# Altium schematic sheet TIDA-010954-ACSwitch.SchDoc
size 431 x 279 mm; Date: Not shown in title block; ApprovedBy: Not shown in title block; CheckedBy: Not shown in title block; Author: Not shown in title block; CompanyName: Not shown in title block; Engineer: Not shown in title block; Organization: Not shown in title block; Address1: Not shown in title block; Address2: Not shown in title block; Address3: Not shown in title block; Address4: Not shown in title block; DocumentNumber: 2; Revision: Use project parameter SCH_Rev; SheetNumber: 3; SheetTotal: 9; PageSetup: Record=PageOptions¦CenterHorizontal=True¦CenterVertical=True¦PrintScale=1.00¦XCorrection=1.00¦YCorrection=1.00¦PrintKind=0¦BorderSize=5000000¦LeftOffset=0¦BottomOffset=0¦Orientation=2¦PaperLength=1000¦PaperWidth=1000¦Scale=100¦PaperSource=15¦PrintQuality=600¦MediaType=1¦DitherType=10¦PaperKind=Letter¦PrintScaleMode=1
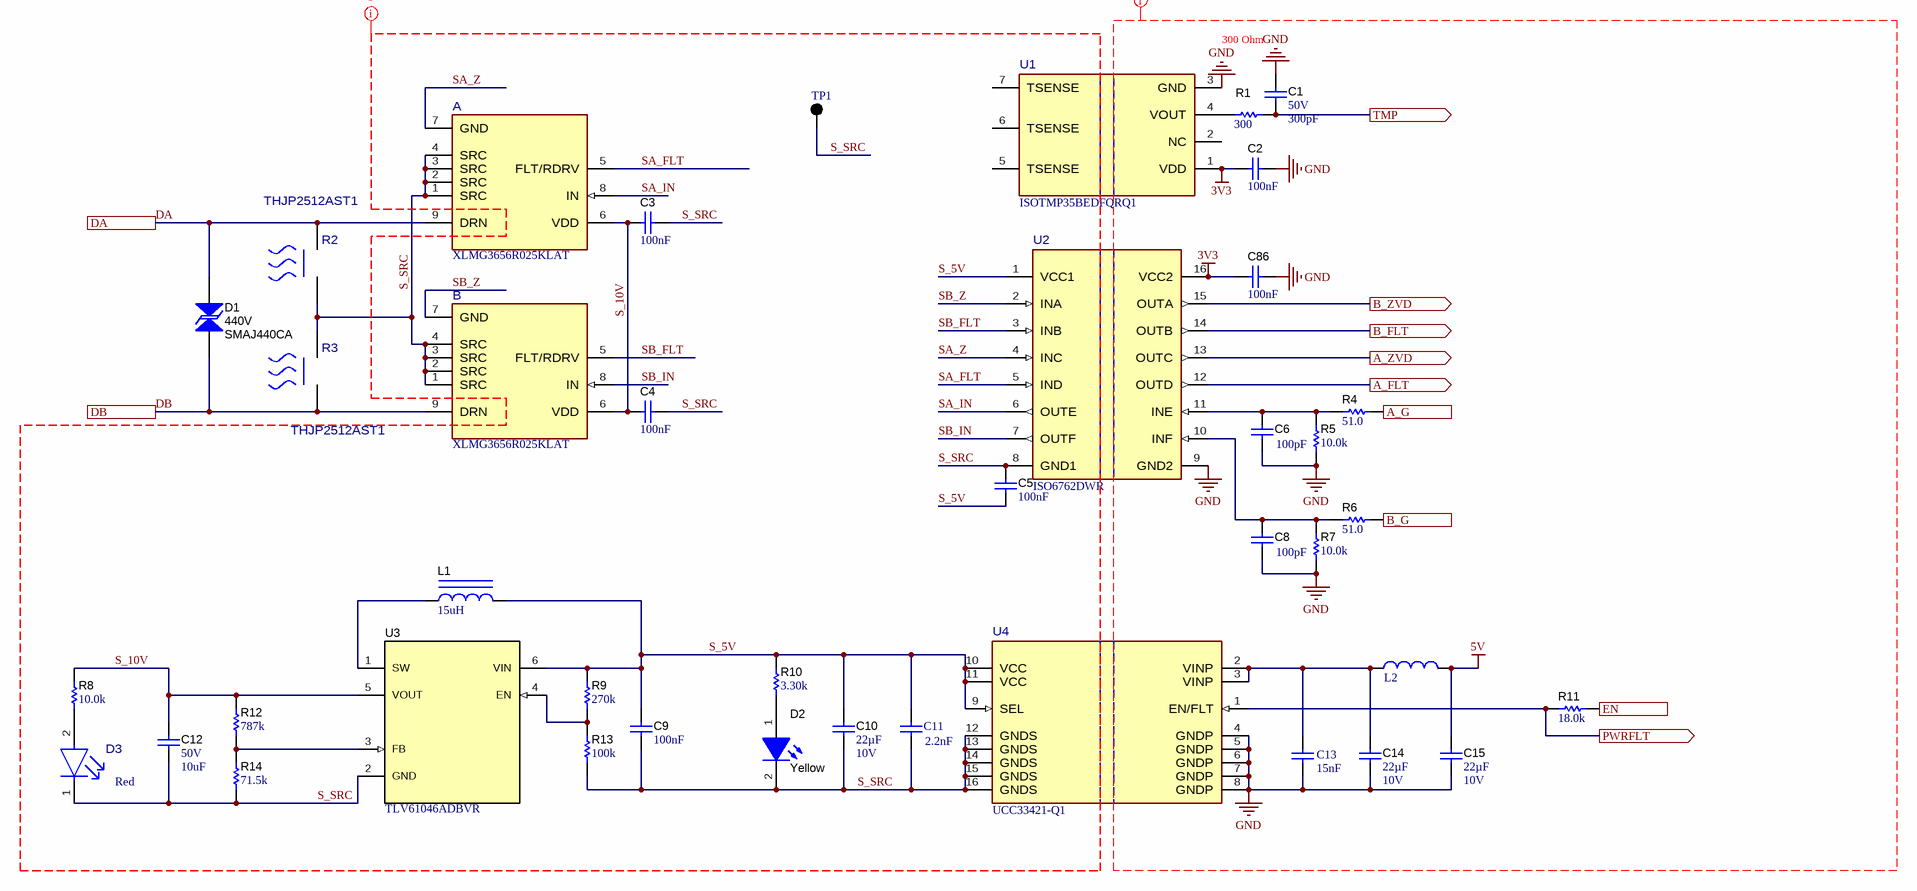
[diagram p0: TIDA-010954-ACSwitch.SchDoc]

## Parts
A  XLMG3656R025KLAT  [KLA0009A-MFG]
B  XLMG3656R025KLAT  [KLA0009A-MFG]
C1  VDC_V: 50V  ValueDisplayed: 300pF  [0603]  (hidden comment: GRM1885C1H301JA01D)
C2  Cap_F: 100nF  [0603]  (hidden comment: CGA3E2X7R1E104K080AA)
C3  Cap_F: 100nF  [0603]  (hidden comment: CGA3E2X7R1E104K080AA)
C4  Cap_F: 100nF  [0603]  (hidden comment: CGA3E2X7R1E104K080AA)
C5  Cap_F: 100nF  [0603]  (hidden comment: CGA3E2X7R1E104K080AA)
C6  ValueDisplayed: 100pF  [0603]  (hidden comment: GRM1885C1H101JA01D)
C8  ValueDisplayed: 100pF  [0603]  (hidden comment: GRM1885C1H101JA01D)
C9  Cap_F: 100nF  [0603]  (hidden comment: CGA3E2X7R1E104K080AA)
C10  Cap_F: 22µF  VDC_V: 10V  [0805_HV]  (hidden comment: GRM21BZ71A226ME15L)
C11  Cap_F: 2.2nF  [WCAP-CSGP_0402_L1W0.5H0.5]  (hidden comment: 885012205063)
C12  VDC_V: 50V  ValueDisplayed: 10uF  [1206_180]  (hidden comment: GRT31CR61H106KE01L)
C13  Cap_F: 15nF  [WCAP-CSGP_0402_L1W0.5H0.5]  (hidden comment: 885012205051)
C14  Cap_F: 22µF  VDC_V: 10V  [0805_HV]  (hidden comment: GRM21BZ71A226ME15L)
C15  Cap_F: 22µF  VDC_V: 10V  [0805_HV]  (hidden comment: GRM21BZ71A226ME15L)
C86  Cap_F: 100nF  [0603]  (hidden comment: CGA3E2X7R1E104K080AA)
D1  SMAJ440CA  value 440V  [SMA_Bi]
D2  value Yellow  [APT1608_Yellow]  (hidden comment: APT1608SYCK)
D3  Color: Red  [FP-APG1608SURKC_T_0603-MFG]  (hidden comment: APG1608SURKC/T)
L1  ValueDisplayed: 15uH  [SDR0302]  (hidden comment: SDR0302-150ML)
L2  74479763222  [WE-PMI_0603_L1.6W0.8H0.8]  (value not drawn)
R1  ValueDisplayed: 300  [0603]  (hidden comment: RC0603FR-07300RL)
R2  THJP2512AST1  [FP-THJP2512AST1_2512-MFG]
R3  THJP2512AST1  [FP-THJP2512AST1_2512-MFG]
R4  ValueDisplayed: 51.0  [0603]  (hidden comment: RC0603FR-0751RL)
R5  ValueDisplayed: 10.0k  [0603]  (hidden comment: RC0603FR-0710KL)
R6  ValueDisplayed: 51.0  [0603]  (hidden comment: RC0603FR-0751RL)
R7  ValueDisplayed: 10.0k  [0603]  (hidden comment: RC0603FR-0710KL)
R8  ValueDisplayed: 10.0k  [0603]  (hidden comment: RC0603FR-0710KL)
R9  ValueDisplayed: 270k  [0603]  (hidden comment: RC0603FR-07270KL)
R10  ValueDisplayed: 3.30k  [0603]  (hidden comment: RC0603FR-073K3L)
R11  ValueDisplayed: 18.0k  [0603]  (hidden comment: RC0603FR-0718KL)
R12  ValueDisplayed: 787k  [0603]  (hidden comment: RC0603FR-07787KL)
R13  ValueDisplayed: 100k  [0603]  (hidden comment: RC0603FR-07100KL)
R14  ValueDisplayed: 71.5k  [0603]  (hidden comment: RC0603FR-0771K5L)
TP1  5011  [Keystone5011]  (value not drawn)
U1  ISOTMP35BEDFQRQ1  [DFQ0007A-MFG]
U2  ISO6762DWR  [DW0016A-MFG]
U3  TLV61046ADBVR  [DBV0006A_N]
U4  UCC33421-Q1  [DWX0016A-MFG]

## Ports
A_FLT (out), A_G (in), A_ZVD (out), B_FLT (out), B_G (in), B_ZVD (out), DA, DB, EN (in), PWRFLT (out), TMP (out)

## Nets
3V3: C2.1 C86.1 U1.1(VDD) U2.16(VCC2)
5V: C15.1 L2.2
GND: C1.2 C2.2 C6.2 C8.2 C13.1 C14.2 C15.2 C86.2 R5.1 R7.1 U1.3(GND) U2.9(GND2) U4.4(GNDP) U4.5(GNDP) U4.6(GNDP) U4.7(GNDP) U4.8(GNDP)
A_FLT: U2.12(OUTD) ; port A_FLT
A_G: R4.2 ; port A_G
A_ZVD: U2.13(OUTC) ; port A_ZVD
B_FLT: U2.14(OUTB) ; port B_FLT
B_G: R6.2 ; port B_G
B_ZVD: U2.15(OUTA) ; port B_ZVD
DA: A.9(DRN) D1.2 R2.2 ; port DA
DB: B.9(DRN) D1.1 R3.1 ; port DB
EN: R11.2 ; port EN
PWRFLT: R11.1 U4.1(EN/FLT) ; port PWRFLT
S_5V: C5.1 C9.2 C10.1 C11.2 L1.2 R9.2 R10.2 U2.1(VCC1) U3.6(VIN) U4.9(SEL) U4.10(VCC) U4.11(VCC)
S_10V: A.6(VDD) B.6(VDD) C3.1 C4.1 C12.1 R8.2 R12.2 U3.5(VOUT)
S_SRC: A.1(SRC) A.2(SRC) A.3(SRC) A.4(SRC) B.1(SRC) B.2(SRC) B.3(SRC) B.4(SRC) C3.2 C4.2 C5.2 C9.1 C10.2 C11.1 C12.2 D2.2(K) D3.1(CATHODE) R2.1 R3.2 R13.1 R14.1 TP1.1 U2.8(GND1) U3.2(GND) U4.12(GNDS) U4.13(GNDS) U4.14(GNDS) U4.15(GNDS) U4.16(GNDS)
SA_FLT: A.5(FLT/RDRV) U2.5(IND)
SA_IN: A.8(IN) U2.6(OUTE)
SA_Z: A.7(GND) U2.4(INC)
SB_FLT: B.5(FLT/RDRV) U2.3(INB)
SB_IN: B.8(IN) U2.7(OUTF)
SB_Z: B.7(GND) U2.2(INA)
TMP: C1.1 R1.2 ; port TMP
NetC6_1: C6.1 R4.1 R5.2 U2.11(INE)
NetC8_1: C8.1 R6.1 R7.2 U2.10(INF)
NetC13_2: C13.2 C14.1 L2.1 U4.2(VINP) U4.3(VINP)
NetD2_1: D2.1(A) R10.1
NetD3_2: D3.2(ANODE) R8.1
NetL1_1: L1.1 U3.1(SW)
NetR1_1: R1.1 U1.4(VOUT)
NetR9_1: R9.1 R13.2 U3.4(EN)
NetR12_1: R12.1 R14.2 U3.3(FB)

Not connected (* = marked no-connect by the designer): U1 2(NC) 5(TSENSE) 6(TSENSE) 7(TSENSE)

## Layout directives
net class SW_SRC: DA, DB, S_5V, S_10V, S_SRC, SA_FLT, SA_IN, SA_Z, SB_FLT, SB_IN, SB_Z
net class LV: 3V3, 5V, GND

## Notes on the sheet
- 300 Ohm

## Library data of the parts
A B = CMP-0120607-2: Manufacturer: Texas Instruments; Part Number: LMG365x; SizeZ_mm: 2.35mm; AEC Qualified: No; Standoff Height: 0.1mm; AEC Category: Q200; CompType: IC
C1 = CMP-0007206-4: CAP, CERM, 300 pF, 50 V, +/- 5%, C0G/NP0, 0603; Manufacturer: MuRata; TaMin_C: -55°C; Polarized: N; SizeAreaWB_mm2: 4.68; Value1: Unknown; U/M: EA; Value: 300pF; TaMax_C: 125°C; SizeZ_mm: 1; SizeX_mm: 1.6; SizeY_mm: 0.8; SizeArea_mm2: 1.28; AEC Category: Q200
C2-C5 C9 C86 = CMP-0007077-5: CAP, CERM, 0.1 uF, 25 V, +/- 10%, X7R, AEC-Q200 Grade 1, 0603; Manufacturer: TDK; TaMin_C: -55°C; Polarized: N; SizeAreaWB_mm2: 4.68; Value1: Unknown; U/M: EA; Value: 0.1uF; TaMax_C: 125°C; SizeZ_mm: 1; SizeX_mm: 1.6; SizeY_mm: 0.8; Value2: 25V; SizeArea_mm2: 1.28; AEC Qualified: Y; AEC Category: Q200
C6 C8 = CMP-0007171-4: CAP, CERM, 100 pF, 50 V, +/- 5%, C0G/NP0, 0603; Manufacturer: MuRata; TaMin_C: -55°C; Polarized: N; SizeAreaWB_mm2: 4.68; Value1: Unknown; U/M: EA; Value: 100pF; TaMax_C: 125°C; SizeZ_mm: 1; SizeX_mm: 1.6; SizeY_mm: 0.8; Value2: 50V; SizeArea_mm2: 1.28; AEC Category: Q200
C10 C14 C15 = CMP-0008377-2: CAP, CERM, 22 uF, 10 V, +/- 20%, X7R, 0805; Manufacturer: MuRata; SizeY_mm: 1.25; Cap_Case: 0805; SizeArea_mm2: 2.5; AEC Qualified: N; AEC Category: Q200; ValueDisplayed: 22uF; TaMin_C: -55°C; SizeAreaWB_mm2: 6.75; Value1: Unknown; U/M: EA; Value: 22uF; TaMax_C: 125°C; SizeZ_mm: 1.45; SizeX_mm: 2
C11 = CMP-0119293-1: WCAP-CSGP Multilayer Ceramic Chip Capacitor, General Purpose, size 0402, X7R, 2.2nF, 50VDC; Manufacturer: Wurth Elektronik; Capacitance Tolerance: +/-10%; Case/Size Code: 0402; Dissipation Factor: 2.5%; Insulation Resistance: 10GOhm; Rated Voltage (DC): 50V; Technical Reference: X7R0402222K050DFCT10000
C12 = CMP-0009015-2: CAP, CERM, 10 uF, 50 V, +/- 10%, X5R, AEC-Q200 Grade 1, 1206; Manufacturer: MuRata; TaMin_C: -55°C; Polarized: N; SizeAreaWB_mm2: 10.92; Value1: Unknown; U/M: EA; Value: 10uF; TaMax_C: 85°C; SizeZ_mm: 1.8; SizeX_mm: 3.2; SizeY_mm: 1.6; Cap_Case: 1206; SizeArea_mm2: 5.12; AEC Qualified: Y; Cap_F: 10µF; AEC Grade: 1; AEC Category: Q200
C13 = CMP-0115362-1: WCAP-CSGP Multilayer Ceramic Chip Capacitor, General Purpose, size 0402, X7R, 15nF, 25VDC; Manufacturer: Wurth Elektronik; Capacitance Tolerance: +/-10%; Case/Size Code: 0402; Dissipation Factor: 3.5%; Insulation Resistance: 10GOhm; Rated Voltage (DC): 25V; Technical Reference: X7R0402153K025DFCT10000
D1 = CMP-0085046-1: Diode, TVS, Bi, 440 V, 713 Vc, 400 W, 0.6 A, SMA (non-polarized); Manufacturer: Littelfuse; Vbr_Max: 543V; Vbr_Min: 492V; Ppk: 400W; SizeY_mm: 2.575; Value1: 713V; SizeArea_mm2: 13.068125; SizeX_mm: 5.075; AEC Category: Q101; SizeAreaWB_mm2: 32.368125; SizeZ_mm: 2.65; RJA_CperW: 120; Ipp: 600mA; AEC Qualified: N
D2 = CMP-0002944-3: LED, Yellow, SMD; Manufacturer: Kingbright; Value2: 2.5V; Ir_A: 10µA; Tjmax_C: 85°C; Value1: W; Io_A: 20mA; Vr_V: 5V; Angle: 120
D3 = CMP-0091305-2: Red 630nm LED Indication - Discrete 2V 0603 (1608 Metric); Manufacturer: Kingbright; AEC Qualified: No; Import Ts: 1521847491; Forward Current: 20mA; Vr_V: 5V; Ciiva Ids: 1546259; Luminous Intensity: 110mcd; Power_TotalModule: 75mW; Tjmax_C: 115°C; Led Orientation: Top View; SizeZ_mm: 0.28mm; LambdaP: 645nm; Angle: 120°
L1 = CMP-0057419-2: Inductor, Drum Core, Ferrite, 15 uH, 0.65 A, 0.4 ohm, SMD; Manufacturer: Bourns; Isat: 0.86A @ 10% inductance drop; Irms: 0.65A @ 40C rise; Green_Lifecycle: Active; SizeAreaWB_mm2: 15.2; DCR_ohm: 4d; Green_REACh: Passed; Value1: 0.4 ohm; Value: 15uH; Imax_A: 6.5dA; SizeZ_mm: 2.5; SizeX_mm: 3; SizeY_mm: 2.8; Value2: 0.65A; SizeArea_mm2: 8.4; Ind_H: 15µH; AEC Category: Q200
L2 = CMP-0100992-1: WE-PMI SMT Power Multilayer Inductor, size 0603, 2.2uH, 0.8A, 375mOhm; Manufacturer: Wurth Elektronik; Case/Size Code: 0603; Inductance Tolerance: 20%; Q Factor: 15; Saturation Current: 0.28A; Self Resonant Frequency: 80MHz; Type: Low RDC
R1 = CMP-0023013-5: RES, 300, 1%, 0.1 W, 0603; Manufacturer: Yageo; Power_W: 100mW; TempCo: 100 ppm/C; Value_Code: 300R; Value: 300; SizeX_mm: 1.6; SizeY_mm: 0.8; SizeZ_mm: 1; Value2: 0.1W; SizeArea_mm2: 1.28; AEC Qualified: N; VDC_V: 75V; AEC Category: Q200; SizeAreaWB_mm2: 4.68
R2 R3 = CMP-0122927-1: Thermal Pad 6.40mm x 3.20mm Rectangular; Manufacturer: Vishay; AEC Grade: Grade 0; AEC Qualified: Yes; SizeZ_mm: 0.035inch
R4 R6 = CMP-0023169-5: RES, 51.0, 1%, 0.1 W, 0603; Manufacturer: Yageo; Power_W: 100mW; TempCo: 100 ppm/C; Value_Code: 51R0; Value: 51.0; Res_ohm: 51; SizeX_mm: 1.6; SizeY_mm: 0.8; SizeZ_mm: 1; Value2: 0.1W; SizeArea_mm2: 1.28; AEC Qualified: N; VDC_V: 75V; AEC Category: Q200; SizeAreaWB_mm2: 4.68
R5 R7 R8 = CMP-0022746-5: RES, 10.0 k, 1%, 0.1 W, 0603; Manufacturer: Yageo; Power_W: 100mW; TempCo: 100 ppm/C; Value_Code: 10k0; Value: 10.0k; EIA_Code: E96; Res_ohm: 10k; SizeX_mm: 1.6; SizeY_mm: 0.8; SizeZ_mm: 1; Value2: 0.1W; SizeArea_mm2: 1.28; AEC Qualified: N; VDC_V: 75V; AEC Category: Q200; SizeAreaWB_mm2: 4.68
R9 = CMP-0022961-4: RES, 270 k, 1%, 0.1 W, 0603; Manufacturer: Yageo; Power_W: 100mW; TempCo: 100 ppm/C; Value: 270k; SizeX_mm: 1.6; SizeY_mm: 0.8; SizeZ_mm: 1; Value2: 0.1W; SizeArea_mm2: 1.28; AEC Qualified: N; VDC_V: 75V; AEC Category: Q200; SizeAreaWB_mm2: 4.68
R10 = CMP-0023081-5: RES, 3.30 k, 1%, 0.1 W, 0603; Manufacturer: Yageo; Power_W: 100mW; TempCo: 100 ppm/C; Value_Code: 3k30; Value: 3.30k; Res_ohm: 3.3k; SizeX_mm: 1.6; SizeY_mm: 0.8; SizeZ_mm: 1; Value2: 0.1W; SizeArea_mm2: 1.28; AEC Qualified: N; VDC_V: 75V; AEC Category: Q200; SizeAreaWB_mm2: 4.68
R11 = CMP-0022852-5: RES, 18.0 k, 1%, 0.1 W, 0603; Manufacturer: Yageo; Power_W: 100mW; TempCo: 100 ppm/C; Value_Code: 18k0; Value: 18.0k; Res_ohm: 18k; SizeX_mm: 1.6; SizeY_mm: 0.8; SizeZ_mm: 1; Value2: 0.1W; SizeArea_mm2: 1.28; AEC Qualified: N; VDC_V: 75V; AEC Category: Q200; SizeAreaWB_mm2: 4.68
R12 = CMP-0023273-4: RES, 787 k, 1%, 0.1 W, 0603; Manufacturer: Yageo; Power_W: 100mW; TempCo: 100 ppm/C; Value: 787k; EIA_Code: E96; SizeX_mm: 1.6; SizeY_mm: 0.8; SizeZ_mm: 1; Value2: 0.1W; SizeArea_mm2: 1.28; AEC Qualified: N; VDC_V: 75V; AEC Category: Q200; SizeAreaWB_mm2: 4.68
R13 = CMP-0022735-5: RES, 100 k, 1%, 0.1 W, 0603; Manufacturer: Yageo; Power_W: 100mW; TempCo: 100 ppm/C; Value: 100k; EIA_Code: E96; SizeX_mm: 1.6; SizeY_mm: 0.8; SizeZ_mm: 1; Value2: 0.1W; SizeArea_mm2: 1.28; AEC Qualified: N; VDC_V: 75V; AEC Category: Q200; SizeAreaWB_mm2: 4.68
R14 = CMP-0023259-5: RES, 71.5 k, 1%, 0.1 W, 0603; Manufacturer: Yageo; Power_W: 100mW; TempCo: 100 ppm/C; Value_Code: 71k5; Value: 71.5k; EIA_Code: E96; SizeX_mm: 1.6; SizeY_mm: 0.8; SizeZ_mm: 1; Value2: 0.1W; SizeArea_mm2: 1.28; AEC Qualified: N; VDC_V: 75V; AEC Category: Q200; SizeAreaWB_mm2: 4.68
TP1 = CMP-0055148-2: Test Point, Multipurpose, Black, TH; Manufacturer: Keystone Electronics; CNHeader: FALSE; ContactFinish: Silver; Green_REACh: Passed; Green_Lifecycle: Active; CT: TRUE
U1 = CMP-0122473-1: Automotive ±1.5°C, 3-kVRMS Isolated Temperature Sensor With Analog Output With < 2 Seconds Response Time and 500VRMS Working Voltage; Manufacturer: Texas Instruments; SizeZ_mm: 1.75mm; AEC Qualified: Yes; AEC Grade: Grade 0; Max Supply Voltage: 5.5V; Min Supply Voltage: 2.3V; Operating Supply Current: 10uA; Sensor Output: Analog Voltage; Standoff Height: 0.11mm; TaMax_C: +150°C; TaMin_C: -40°C; TJmax_C: +155°C
U2 = CMP-0096105-1: General purpose, 50-Mbps, six-channel (4/2) digital isolator 16-SOIC -40 to 125; Manufacturer: Texas Instruments; Min Supply Voltage: 1.71V; TJmax_C: +150°C; TaMax_C: +125°C; AEC Qualified: No; Max Supply Voltage: 5.5V; Standoff Height: 0.1mm; SizeZ_mm: 2.65mm; Interface: SPI,UART,CAN,RS-232,RS-485; TaMin_C: -40°C
U3 = CMP-0013231-2: 28-V Output Voltage Boost Converter with Power Diode and Isolation Switch, DBV0006A (SOT-6); Manufacturer: Texas Instruments; Alternate PartNumber: TLV61046ADBVT; SizeX_mm: 2.8; SizeY_mm: 2.9; CompType: IC; SizeZ_mm: 1.45; SizeArea_mm2: 8.12; SizeAreaWB_mm2: 14.82; U/M: EA
U4 = CMP-0120108-2: 1.5W, High-Density, >5 kVRMS Isolated DC-DC Converter; Manufacturer: Texas Instruments; SizeZ_mm: 2.6mm; AEC Qualified: No; Max Supply Voltage: 5.5V; Min Supply Voltage: 4.5V; Number Of Outputs: 1; Output Type: AdjustableProgrammable; Output Voltage: 5/5.5V; Standoff Height: 0.14mm; AEC Category: Q200; CompType: IC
